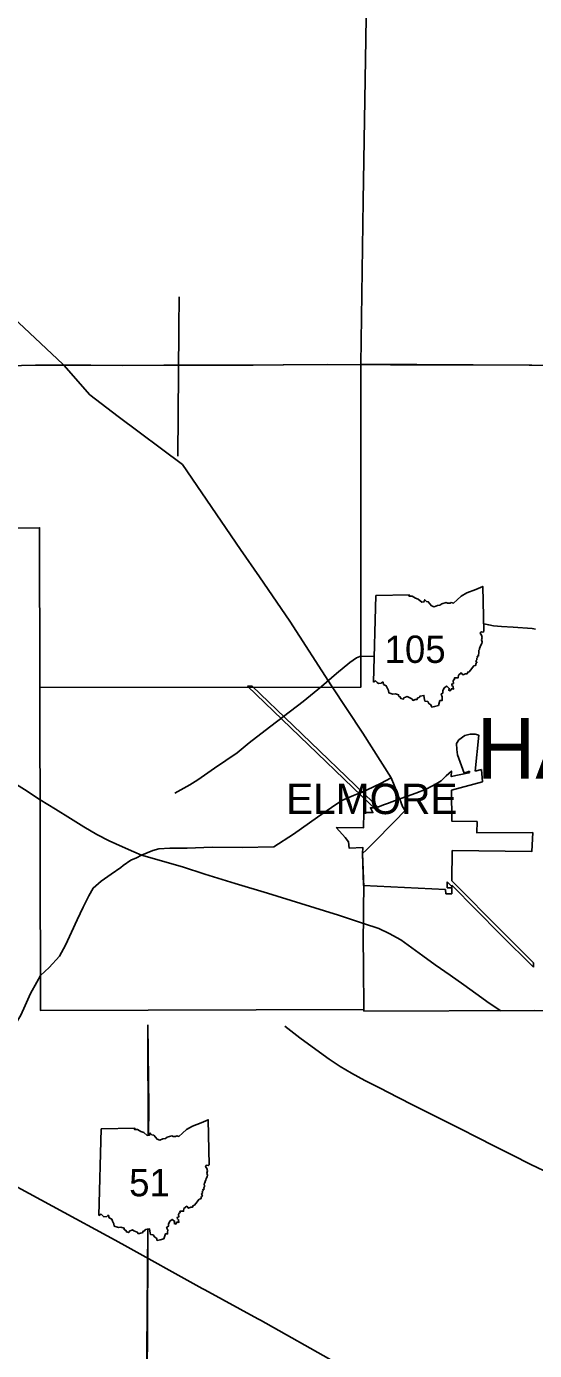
# Model space of a CAD drawing. Extents: x -232 to 448, y 619 to 1059.
# Drawn here: x 229.69 to 246.85, y 845.39 to 890.09 of the extents above; entities that cross this region are included whole.
import ezdxf

# ---------------------------------------------------------------- set-up
doc = ezdxf.new("R2010")
doc.units = 0
doc.layers.add('Default', color=7, linetype='Continuous')

msp = doc.modelspace()

# ---------------------------------------------------------------- linework, layer by layer
at = {"layer": 'Default'}
for p, q in [((241.407, 867.949), (241.489, 870.877)), ((241.407, 867.949), (241.489, 870.877)), ((244.848, 864.95), (244.973, 866.162)), ((244.474, 864.883), (244.651, 864.949)), ((241.079, 861.092), (243.848, 860.957)), ((243.848, 860.957), (243.853, 860.806)), ((243.904, 861.005), (243.898, 861.208)), ((243.898, 861.208), (243.904, 861.005)), ((244.055, 861.009), (243.904, 861.005)), ((243.904, 861.005), (244.055, 861.009)), ((243.853, 860.806), (244.058, 860.811)), ((232.132, 849.943), (232.214, 852.872)), ((232.132, 849.943), (232.214, 852.872))]:
    msp.add_line(p, q, dxfattribs=at)
for points in [[(241.234, 894.977), (241.156, 889.655), (241.062, 884.206), (240.982, 878.692)], [(230.952, 878.654), (230.912, 878.691), (228.66, 880.797), (228.639, 880.817), (228.581, 880.871), (227.191, 882.157)], [(234.799, 875.584), (234.836, 879.826), (234.837, 879.928), (234.848, 880.967)], [(226.653, 878.592), (227.198, 878.598), (227.605, 878.603), (229.988, 878.65), (230.341, 878.654), (230.952, 878.654)], [(240.982, 878.692), (240.978, 867.781), (230.138, 867.773)], [(230.952, 878.654), (231.863, 878.649), (232.932, 878.646), (234.33, 878.65), (235.318, 878.65), (235.909, 878.65), (237.342, 878.651), (238.364, 878.661)], [(242.26, 864.097), (242.212, 864.223), (242.005, 864.722), (241.046, 866.228), (239.991, 867.832), (238.58, 870.012), (237.558, 871.509), (236.913, 872.431), (234.955, 875.297), (232.789, 876.924), (231.83, 877.655), (230.952, 878.654)], [(238.364, 878.661), (238.375, 878.661), (239.867, 878.677), (241.988, 878.669), (244.609, 878.668), (246.763, 878.658), (249.369, 878.629), (252.168, 878.652), (257.625, 878.588)], [(240.982, 878.692), (246.674, 878.656), (273.933, 878.589)], [(208.907, 873.052), (220.052, 873.095), (230.127, 873.163), (230.138, 867.773)], [(241.489, 870.877), (242.625, 870.897), (242.608, 870.861), (242.715, 870.854), (242.829, 870.791), (242.925, 870.752), (243.043, 870.658), (243.113, 870.659), (243.143, 870.736), (243.197, 870.677), (243.261, 870.666), (243.372, 870.526), (243.464, 870.496), (243.573, 870.544), (243.655, 870.552), (243.715, 870.599), (243.871, 870.64), (243.914, 870.616), (243.997, 870.62), (244.038, 870.638), (244.11, 870.622), (244.237, 870.729), (244.368, 870.854), (244.568, 870.973), (244.868, 871.085), (245.105, 871.186), (245.139, 869.666)], [(241.489, 870.877), (242.625, 870.897), (242.608, 870.861), (242.715, 870.854), (242.829, 870.791), (242.925, 870.752), (243.043, 870.658), (243.113, 870.659), (243.143, 870.736), (243.197, 870.677), (243.261, 870.666), (243.372, 870.526), (243.464, 870.496), (243.573, 870.544), (243.655, 870.552), (243.715, 870.599), (243.871, 870.64), (243.914, 870.616), (243.997, 870.62), (244.038, 870.638), (244.11, 870.622), (244.237, 870.729), (244.368, 870.854), (244.568, 870.973), (244.868, 871.085), (245.105, 871.186), (245.139, 869.666)], [(245.134, 869.925), (245.308, 869.885), (245.464, 869.855), (245.731, 869.829), (246.135, 869.806), (246.77, 869.759), (246.889, 869.741)], [(245.139, 869.666), (245.104, 869.644), (245.05, 869.654), (245.013, 869.612), (245.059, 869.541), (245.08, 869.465), (245.061, 869.383), (245.08, 869.314), (245.067, 869.257), (245.033, 869.2), (245.021, 869.146), (244.992, 869.089), (244.994, 869.057), (244.967, 869.032), (244.972, 868.936), (244.958, 868.884), (244.962, 868.838), (244.917, 868.826), (244.928, 868.789), (244.899, 868.76), (244.905, 868.71), (244.873, 868.678), (244.904, 868.614), (244.879, 868.594), (244.858, 868.517), (244.8, 868.501), (244.685, 868.359), (244.644, 868.305), (244.598, 868.292), (244.573, 868.237), (244.516, 868.237), (244.431, 868.199), (244.376, 868.264), (244.279, 868.185), (244.268, 868.094), (244.146, 868.097), (244.151, 868.051), (244.123, 868.037), (244.098, 867.991), (244.113, 867.909), (244.056, 867.888), (244.063, 867.84), (244.099, 867.811), (244.115, 867.72), (244.055, 867.738), (244.005, 867.661), (243.954, 867.679), (243.97, 867.744), (243.884, 867.823), (243.802, 867.76), (243.759, 867.66), (243.759, 867.592), (243.698, 867.552), (243.737, 867.456), (243.73, 867.391), (243.731, 867.328), (243.655, 867.331), (243.608, 867.162)], [(245.139, 869.666), (245.104, 869.644), (245.05, 869.654), (245.013, 869.612), (245.059, 869.541), (245.08, 869.465), (245.061, 869.383), (245.08, 869.314), (245.067, 869.257), (245.033, 869.2), (245.021, 869.146), (244.992, 869.089), (244.994, 869.057), (244.967, 869.032), (244.972, 868.936), (244.958, 868.884), (244.962, 868.838), (244.917, 868.826), (244.928, 868.789), (244.899, 868.76), (244.905, 868.71), (244.873, 868.678), (244.904, 868.614), (244.879, 868.594), (244.858, 868.517), (244.8, 868.501), (244.685, 868.359), (244.644, 868.305), (244.598, 868.292), (244.573, 868.237), (244.516, 868.237), (244.431, 868.199), (244.376, 868.264), (244.279, 868.185), (244.268, 868.094), (244.146, 868.097), (244.151, 868.051), (244.123, 868.037), (244.098, 867.991), (244.113, 867.909), (244.056, 867.888), (244.063, 867.84), (244.099, 867.811), (244.115, 867.72), (244.055, 867.738), (244.005, 867.661), (243.954, 867.679), (243.97, 867.744), (243.884, 867.823), (243.802, 867.76), (243.759, 867.66), (243.759, 867.592), (243.698, 867.552), (243.737, 867.456), (243.73, 867.391), (243.731, 867.328), (243.655, 867.331), (243.608, 867.162)], [(234.703, 864.206), (235.208, 864.492), (235.471, 864.656), (236.043, 865.045), (236.804, 865.572), (237.21, 865.899), (237.602, 866.203), (237.943, 866.468), (238.372, 866.789), (239.04, 867.304), (239.66, 867.801), (240.164, 868.245), (240.614, 868.62), (240.833, 868.77), (240.954, 868.824), (241.432, 868.835)], [(230.138, 867.773), (230.16, 856.869), (241.087, 856.9), (241.086, 856.841)], [(237.312, 867.814), (237.152, 867.812)], [(237.152, 867.812), (238.622, 866.415), (241.315, 863.824), (241.433, 863.712)], [(241.556, 863.737), (241.385, 863.899), (238.693, 866.489), (237.312, 867.814)], [(243.608, 867.162), (243.476, 867.13), (243.384, 867.111), (243.351, 867.188), (243.285, 867.228), (243.243, 867.305), (243.148, 867.315), (243.126, 867.421), (243.115, 867.506), (242.986, 867.485), (242.95, 867.433), (242.904, 867.419), (242.878, 867.366), (242.815, 867.362), (242.748, 867.337), (242.704, 867.388), (242.595, 867.441), (242.545, 867.467), (242.442, 867.426), (242.42, 867.376), (242.338, 867.398), (242.318, 867.453), (242.269, 867.47), (242.258, 867.528), (242.151, 867.559), (242.07, 867.547), (241.927, 867.594), (241.918, 867.67), (241.869, 867.764), (241.843, 867.829), (241.753, 867.878), (241.734, 867.956), (241.705, 867.953), (241.679, 867.922), (241.578, 867.908), (241.538, 867.939), (241.482, 867.993), (241.407, 867.949)], [(243.608, 867.162), (243.476, 867.13), (243.384, 867.111), (243.351, 867.188), (243.285, 867.228), (243.243, 867.305), (243.148, 867.315), (243.126, 867.421), (243.115, 867.506), (242.986, 867.485), (242.95, 867.433), (242.904, 867.419), (242.878, 867.366), (242.815, 867.362), (242.748, 867.337), (242.704, 867.388), (242.595, 867.441), (242.545, 867.467), (242.442, 867.426), (242.42, 867.376), (242.338, 867.398), (242.318, 867.453), (242.269, 867.47), (242.258, 867.528), (242.151, 867.559), (242.07, 867.547), (241.927, 867.594), (241.918, 867.67), (241.869, 867.764), (241.843, 867.829), (241.753, 867.878), (241.734, 867.956), (241.705, 867.953), (241.679, 867.922), (241.578, 867.908), (241.538, 867.939), (241.482, 867.993), (241.407, 867.949)], [(225, 867.203), (225.191, 867.084), (225.77, 866.722), (226.363, 866.349), (227.002, 865.954), (227.631, 865.567), (228.331, 865.133), (228.959, 864.741), (229.624, 864.327), (230.146, 863.98)], [(244.973, 866.162), (244.85, 866.196), (244.677, 866.193), (244.501, 866.157), (244.29, 866.002), (244.22, 865.877), (244.229, 865.682), (244.254, 865.497), (244.474, 864.883)], [(244.658, 864.902), (244.632, 864.895), (244.041, 864.766), (244.044, 864.953), (243.865, 864.794), (243.701, 864.618), (243.526, 864.517), (243.191, 864.344), (242.839, 864.206), (242.562, 864.103), (242.264, 864.004), (241.887, 863.852), (241.748, 863.807), (241.556, 863.737)], [(244.651, 864.949), (244.658, 864.902)], [(245.066, 865.009), (244.848, 864.95)], [(245.098, 864.584), (245.066, 865.009)], [(240.998, 864.233), (241.199, 864.317), (241.644, 864.531), (242.005, 864.722)], [(244.912, 863.247), (244.062, 863.258), (244.048, 864.304), (245.098, 864.584)], [(234.55, 862.348), (235.119, 862.35), (235.956, 862.382), (236.978, 862.368), (238.047, 862.389), (238.71, 862.823), (239.52, 863.397), (239.992, 863.722), (240.337, 863.957), (240.733, 864.121), (240.9, 864.191)], [(240.9, 864.191), (240.998, 864.233)], [(242.297, 864.001), (242.26, 864.097)], [(230.146, 863.98), (230.666, 863.661), (231.178, 863.345), (231.622, 863.069), (232.06, 862.809), (232.48, 862.594), (232.933, 862.388), (233.316, 862.223), (233.576, 862.111), (234.959, 861.713), (235.71, 861.474), (236.738, 861.161), (237.825, 860.83), (238.96, 860.48), (240.228, 860.084), (241.075, 859.806), (241.59, 859.632), (241.942, 859.47), (242.335, 859.249), (242.712, 858.988), (243.084, 858.712), (243.497, 858.415), (244.003, 858.057), (244.461, 857.729), (244.87, 857.438), (245.318, 857.113), (245.713, 856.861)], [(241.433, 863.712), (241.306, 863.715), (241.393, 863.55), (241.081, 863.554), (241.074, 863.036), (240.149, 863.05)], [(242.125, 863.251), (242.477, 863.617), (242.472, 863.626)], [(242.472, 863.626), (242.389, 863.759), (242.297, 864.001)], [(241.171, 862.296), (241.56, 862.677), (241.966, 863.087), (242.125, 863.251)], [(244.074, 862.273), (246.761, 862.232), (246.793, 862.875), (244.907, 862.861), (244.912, 863.247)], [(240.149, 863.05), (240.259, 862.924), (240.45, 862.707), (240.562, 862.56), (240.592, 862.344), (241.052, 862.367), (241.045, 862.173), (241.079, 861.092)], [(232.959, 861.76), (233.209, 861.938), (233.409, 862.027), (233.576, 862.111), (233.96, 862.273), (234.155, 862.327), (234.534, 862.348), (234.55, 862.348)], [(241.08, 860.998), (241.081, 861.029), (241.045, 862.173), (241.171, 862.296)], [(244.059, 861.245), (244.074, 862.273)], [(230.157, 858.053), (230.455, 858.323), (230.805, 858.705), (231.001, 859.074), (231.209, 859.517), (231.403, 859.929), (231.605, 860.358), (231.799, 860.739), (231.941, 861), (232.207, 861.235), (232.55, 861.473), (232.874, 861.699), (232.959, 861.76)], [(241.078, 860.376), (241.08, 860.998)], [(243.898, 861.208), (244.057, 861.05)], [(244.057, 861.05), (243.898, 861.208)], [(244.054, 860.947), (244.055, 861.009)], [(244.058, 860.811), (244.054, 860.947)], [(244.055, 861.009), (244.057, 861.05)], [(244.057, 861.05), (244.057, 861.101)], [(244.057, 861.101), (245.705, 859.434), (246.814, 858.327)], [(246.814, 858.472), (245.777, 859.507), (244.059, 861.245)], [(241.07, 858.667), (241.068, 858.994), (241.065, 859.453), (241.075, 859.806), (241.078, 860.376)], [(241.087, 856.9), (241.081, 857.361), (241.077, 857.908), (241.072, 858.432), (241.07, 858.667)], [(246.814, 858.327), (246.814, 858.472)], [(227.465, 855.362), (227.521, 855.381), (227.933, 855.519), (228.196, 855.616), (228.469, 855.781), (228.834, 856.05), (229.165, 856.305), (229.361, 856.481), (229.501, 856.708), (229.643, 857.034), (229.82, 857.438), (230.041, 857.83), (230.157, 858.053)], [(241.086, 856.841), (246.842, 856.866), (255.063, 856.795), (273.979, 856.774)], [(233.81, 852.653), (233.818, 853.602), (233.785, 856.383)], [(233.793, 852.648), (233.785, 856.324)], [(238.411, 856.344), (238.927, 855.942), (239.467, 855.554), (239.91, 855.225), (240.283, 854.974), (240.664, 854.747), (241.114, 854.51), (241.616, 854.256), (242.241, 853.935), (242.757, 853.671), (243.275, 853.413), (243.783, 853.159), (244.369, 852.861), (244.904, 852.592), (245.502, 852.29), (246.086, 851.997), (246.731, 851.672), (247.396, 851.356)], [(232.214, 852.872), (233.35, 852.891), (233.332, 852.855), (233.439, 852.848), (233.553, 852.785), (233.65, 852.746), (233.767, 852.653), (233.838, 852.654), (233.868, 852.73), (233.922, 852.671), (233.986, 852.661), (234.097, 852.521), (234.188, 852.49), (234.298, 852.538), (234.38, 852.546), (234.439, 852.594), (234.595, 852.634), (234.639, 852.61), (234.721, 852.615), (234.763, 852.633), (234.835, 852.617), (234.962, 852.723), (235.092, 852.849), (235.293, 852.967), (235.593, 853.08), (235.83, 853.18), (235.864, 851.66)], [(232.214, 852.872), (233.35, 852.891), (233.332, 852.855), (233.439, 852.848), (233.553, 852.785), (233.65, 852.746), (233.767, 852.653), (233.838, 852.654), (233.868, 852.73), (233.922, 852.671), (233.986, 852.661), (234.097, 852.521), (234.188, 852.49), (234.298, 852.538), (234.38, 852.546), (234.439, 852.594), (234.595, 852.634), (234.639, 852.61), (234.721, 852.615), (234.763, 852.633), (234.835, 852.617), (234.962, 852.723), (235.092, 852.849), (235.293, 852.967), (235.593, 853.08), (235.83, 853.18), (235.864, 851.66)], [(226.599, 852.432), (228.217, 851.534), (228.217, 851.534), (228.313, 851.482), (232.812, 849.043), (232.859, 849.016), (232.907, 848.99), (235.621, 847.485), (235.668, 847.458), (235.715, 847.433), (237.498, 846.46), (237.53, 846.442), (237.591, 846.408), (240.153, 844.97), (240.185, 844.951), (240.246, 844.917), (240.758, 844.631)], [(235.864, 851.66), (235.829, 851.639), (235.774, 851.649), (235.738, 851.606), (235.783, 851.535), (235.805, 851.46), (235.786, 851.377), (235.804, 851.309), (235.792, 851.251), (235.757, 851.195), (235.746, 851.14), (235.716, 851.083), (235.719, 851.051), (235.691, 851.026), (235.696, 850.931), (235.682, 850.878), (235.687, 850.833), (235.642, 850.821), (235.652, 850.783), (235.624, 850.754), (235.63, 850.704), (235.597, 850.673), (235.629, 850.609), (235.604, 850.588), (235.583, 850.511), (235.525, 850.495), (235.409, 850.353), (235.368, 850.3), (235.323, 850.286), (235.297, 850.231), (235.241, 850.231), (235.156, 850.193), (235.1, 850.259), (235.004, 850.18), (234.993, 850.088), (234.87, 850.091), (234.875, 850.045), (234.848, 850.031), (234.823, 849.985), (234.837, 849.903), (234.78, 849.882), (234.787, 849.834), (234.824, 849.805), (234.84, 849.714), (234.779, 849.732), (234.729, 849.656), (234.678, 849.674), (234.695, 849.739), (234.608, 849.817), (234.526, 849.754), (234.484, 849.654), (234.483, 849.587), (234.422, 849.546), (234.461, 849.451), (234.454, 849.385), (234.455, 849.323), (234.379, 849.325), (234.333, 849.157)], [(235.864, 851.66), (235.829, 851.639), (235.774, 851.649), (235.738, 851.606), (235.783, 851.535), (235.805, 851.46), (235.786, 851.377), (235.804, 851.309), (235.792, 851.251), (235.757, 851.195), (235.746, 851.14), (235.716, 851.083), (235.719, 851.051), (235.691, 851.026), (235.696, 850.931), (235.682, 850.878), (235.687, 850.833), (235.642, 850.821), (235.652, 850.783), (235.624, 850.754), (235.63, 850.704), (235.597, 850.673), (235.629, 850.609), (235.604, 850.588), (235.583, 850.511), (235.525, 850.495), (235.409, 850.353), (235.368, 850.3), (235.323, 850.286), (235.297, 850.231), (235.241, 850.231), (235.156, 850.193), (235.1, 850.259), (235.004, 850.18), (234.993, 850.088), (234.87, 850.091), (234.875, 850.045), (234.848, 850.031), (234.823, 849.985), (234.837, 849.903), (234.78, 849.882), (234.787, 849.834), (234.824, 849.805), (234.84, 849.714), (234.779, 849.732), (234.729, 849.656), (234.678, 849.674), (234.695, 849.739), (234.608, 849.817), (234.526, 849.754), (234.484, 849.654), (234.483, 849.587), (234.422, 849.546), (234.461, 849.451), (234.454, 849.385), (234.455, 849.323), (234.379, 849.325), (234.333, 849.157)], [(234.333, 849.157), (234.2, 849.125), (234.108, 849.105), (234.076, 849.182), (234.01, 849.222), (233.967, 849.299), (233.873, 849.31), (233.85, 849.415), (233.84, 849.501), (233.71, 849.48), (233.675, 849.427), (233.629, 849.413), (233.602, 849.36), (233.54, 849.356), (233.473, 849.331), (233.429, 849.383), (233.319, 849.435), (233.27, 849.462), (233.166, 849.42), (233.144, 849.371), (233.062, 849.392), (233.043, 849.447), (232.993, 849.464), (232.982, 849.522), (232.876, 849.553), (232.795, 849.541), (232.651, 849.588), (232.642, 849.665), (232.594, 849.758), (232.568, 849.823), (232.477, 849.873), (232.459, 849.95), (232.43, 849.948), (232.403, 849.916), (232.303, 849.902), (232.262, 849.934), (232.206, 849.987), (232.132, 849.943)], [(234.333, 849.157), (234.2, 849.125), (234.108, 849.105), (234.076, 849.182), (234.01, 849.222), (233.967, 849.299), (233.873, 849.31), (233.85, 849.415), (233.84, 849.501), (233.71, 849.48), (233.675, 849.427), (233.629, 849.413), (233.602, 849.36), (233.54, 849.356), (233.473, 849.331), (233.429, 849.383), (233.319, 849.435), (233.27, 849.462), (233.166, 849.42), (233.144, 849.371), (233.062, 849.392), (233.043, 849.447), (232.993, 849.464), (232.982, 849.522), (232.876, 849.553), (232.795, 849.541), (232.651, 849.588), (232.642, 849.665), (232.594, 849.758), (232.568, 849.823), (232.477, 849.873), (232.459, 849.95), (232.43, 849.948), (232.403, 849.916), (232.303, 849.902), (232.262, 849.934), (232.206, 849.987), (232.132, 849.943)], [(233.53, 837.198), (233.645, 841.455), (233.775, 845.506), (233.792, 849.493)], [(233.738, 843.957), (233.785, 849.503)]]:
    msp.add_lwpolyline(points, dxfattribs=at)

# ---------------------------------------------------------------- texts
for s, height, p in [('105', 0.9234, (241.788, 868.602)), ('HARRIS', 2.052, (244.898, 864.692)), ('ELMORE', 1.026, (238.458, 863.498)), ('51', 0.9234, (233.156, 850.596))]:
    msp.add_text(s, height=height, dxfattribs=at).set_placement(p)

doc.saveas('drawing.dxf')
